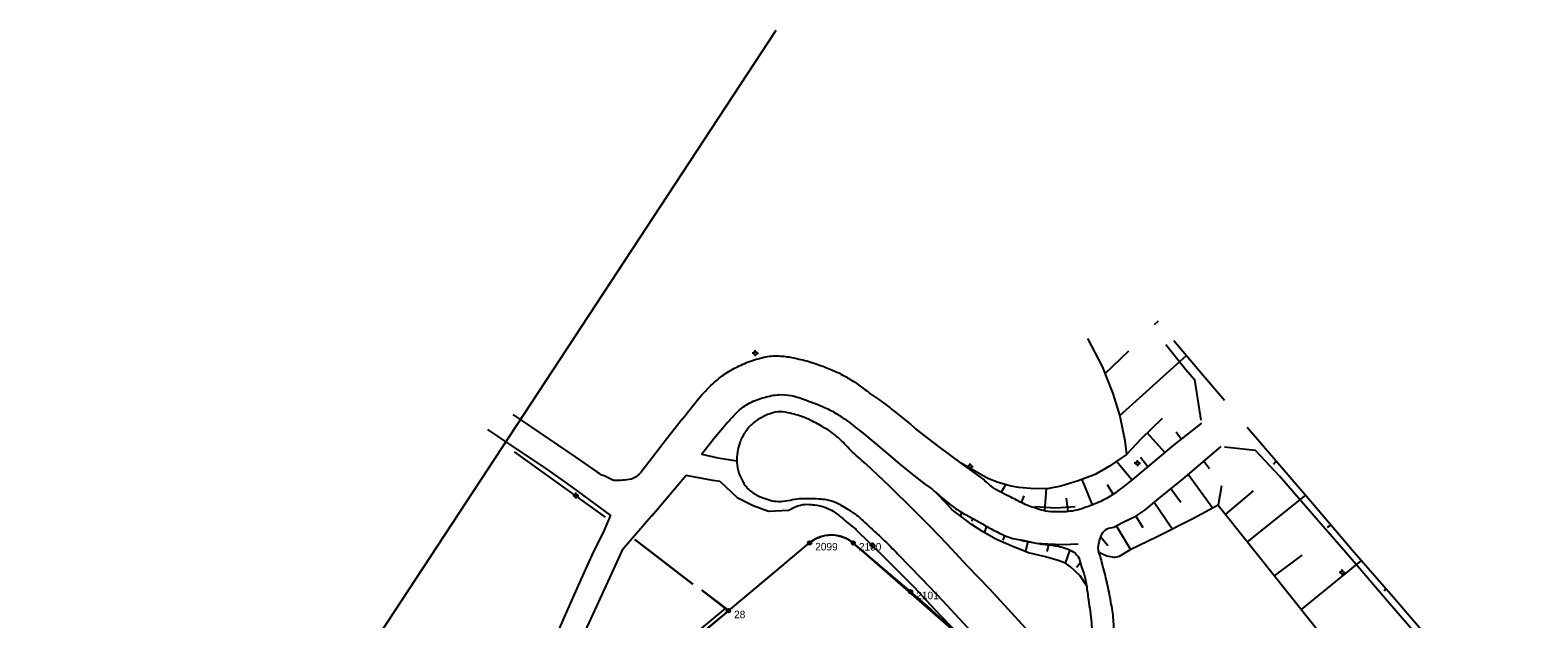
# Model space of a CAD drawing. Extents: x 1517478 to 1518189, y 6494860 to 6495389.
# Drawn here: x 1517883.6 to 1518083.7, y 6495240.6 to 6495318.7 of the extents above; entities that cross this region are included whole.
import ezdxf

# ---------------------------------------------------------------- set-up
doc = ezdxf.new("R2010")
doc.units = 0
for name, color, linetype in [('gc_vag', 7, 'Continuous'), ('grans', 7, 'Continuous'), ('granspunkt', 7, 'Continuous'), ('granspunkt_text', 7, 'Continuous'), ('hack', 7, 'Continuous'), ('kvartersgrans', 7, 'Continuous'), ('kvartersytor', 7, 'Continuous'), ('ledningar', 7, 'Continuous'), ('slant_skraffering', 7, 'Continuous'), ('slantfot', 7, 'Continuous'), ('slantkron', 7, 'Continuous'), ('staket', 7, 'Continuous'), ('stolpe_belysning', 7, 'Continuous'), ('vagkant', 7, 'Continuous')]:
    doc.layers.add(name, color=color, linetype=linetype)

msp = doc.modelspace()

# ---------------------------------------------------------------- linework, layer by layer
at = {"layer": 'gc_vag'}
for p, q in [((1517965.26, 6495260.82), (1517964.65, 6495260.03)), ((1517970.67, 6495259.61), (1517966.11, 6495254.21))]:
    msp.add_line(p, q, dxfattribs=at)
for points in [[(1517958.87, 6495260.1), (1517955.99, 6495262.08), (1517950.2, 6495266.03), (1517947.68, 6495267.69)], [(1517998.25, 6495268.16), (1518000.45, 6495266.43), (1518001.2, 6495265.76)], [(1517947.49, 6495263.61), (1517944.35, 6495265.74)], [(1517970.19, 6495267.12), (1517968.06, 6495264.42), (1517965.26, 6495260.82)], [(1517976.19, 6495266.7), (1517974.34, 6495264.49), (1517972.76, 6495262.43), (1517974.85, 6495261.97), (1517977.4, 6495261.55)], [(1517993.91, 6495265.4), (1517997.19, 6495262.67), (1517999.04, 6495261.12), (1518000.89, 6495259.61), (1518002.28, 6495258.52), (1518002.99, 6495258.03)], [(1518010.15, 6495259.08), (1518007.15, 6495261.25), (1518004.22, 6495263.42), (1518001.2, 6495265.76)], [(1518039.04, 6495266.56), (1518035.33, 6495263.64), (1518031.54, 6495260.45), (1518029.88, 6495259.08)], [(1517960.6, 6495254.37), (1517955.6, 6495258.02), (1517952.07, 6495260.53), (1517947.49, 6495263.61)], [(1518041.63, 6495263.45), (1518036.56, 6495259.17), (1518033.37, 6495256.57), (1518031.5, 6495255), (1518030.05, 6495254.06), (1518028.48, 6495253.3), (1518027.42, 6495252.7)], [(1517975.17, 6495258.82), (1517974.19, 6495258.97), (1517970.67, 6495259.61)], [(1517975.17, 6495258.82), (1517977.41, 6495256.72), (1517979.57, 6495255.64), (1517981.57, 6495254.87), (1517984.25, 6495255)], [(1517960.6, 6495254.37), (1517959.63, 6495252.05), (1517958.37, 6495249.52), (1517956.69, 6495245.83), (1517954.9, 6495241.83), (1517953.53, 6495238.72), (1517952.69, 6495236.93), (1517951.8, 6495234.88)], [(1517966.27, 6495254.47), (1517962.16, 6495249.73), (1517959.53, 6495243.94), (1517957.48, 6495239.51), (1517955.85, 6495235.83), (1517954.98, 6495233.83)], [(1517993.02, 6495252.63), (1517997.24, 6495248.49), (1518000.94, 6495244.79), (1518003.63, 6495241.91)], [(1518003.63, 6495241.88), (1518003.63, 6495241.91), (1518007.63, 6495237.7), (1518010.48, 6495234.7), (1518013.14, 6495232.03), (1518016.08, 6495228.73), (1518017.93, 6495226.61)]]:
    msp.add_lwpolyline(points, dxfattribs=at)
for points in [[(1517970.19, 6495267.12), (1517972.31, 6495269.79), (1517974.19, 6495271.79), (1517975.88, 6495273.13), (1517977.7, 6495274.16), (1517979.7, 6495274.95), (1517981.76, 6495275.43), (1517983.64, 6495275.43), (1517985.34, 6495275.13), (1517987.46, 6495274.58), (1517988.79, 6495274.1), (1517990.49, 6495273.43), (1517991.89, 6495272.7), (1517993.34, 6495271.79), (1517994.8, 6495270.7), (1517996.86, 6495269.25), (1517998.25, 6495268.16)], [(1517976.19, 6495266.7), (1517977.52, 6495268.1), (1517979.1, 6495269.25), (1517981.04, 6495269.98), (1517982.98, 6495270.34), (1517984.61, 6495270.22), (1517986.61, 6495269.61), (1517989.04, 6495268.64), (1517990.67, 6495267.79), (1517992.01, 6495266.88), (1517994.1, 6495265.25)], [(1517964.65, 6495260.03), (1517963.69, 6495259.26), (1517962.48, 6495259), (1517961.53, 6495258.95), (1517960.91, 6495259), (1517960.22, 6495259.37), (1517959.48, 6495259.68), (1517958.48, 6495260.37)], [(1518002.9, 6495258.1), (1518003.79, 6495257.38), (1518005.71, 6495255.76), (1518007.62, 6495254.49), (1518009.19, 6495253.64), (1518010.77, 6495252.74), (1518012.34, 6495251.93), (1518013.53, 6495251.42), (1518014.51, 6495251.17), (1518018.34, 6495250.45), (1518020.08, 6495250.23), (1518021.1, 6495249.94), (1518022.12, 6495249.43), (1518022.76, 6495248.7), (1518023.02, 6495247.85), (1518023.36, 6495246.87), (1518023.78, 6495245.04), (1518024.04, 6495243.13)], [(1518029.88, 6495259.08), (1518028.1, 6495257.68), (1518026.44, 6495256.57), (1518024.36, 6495255.64), (1518021.93, 6495254.91), (1518019.81, 6495254.79), (1518018.36, 6495254.91), (1518017.25, 6495255.21), (1518015.42, 6495255.89), (1518013.77, 6495256.74), (1518011.51, 6495257.93), (1518010.15, 6495259.08)], [(1517984.25, 6495255), (1517985.06, 6495255.42), (1517985.85, 6495255.7), (1517986.97, 6495255.79), (1517988, 6495255.67), (1517988.82, 6495255.49), (1517989.55, 6495255.21), (1517990.34, 6495254.76), (1517991, 6495254.27), (1517992.15, 6495253.3), (1517993.24, 6495252.46)], [(1518027.42, 6495252.7), (1518026.48, 6495252.49), (1518025.8, 6495251.81), (1518025.46, 6495250.91), (1518025.33, 6495249.72), (1518025.59, 6495248.87), (1518025.84, 6495247.94)], [(1518025.84, 6495247.94), (1518026.48, 6495245.38), (1518026.99, 6495242.87), (1518027.33, 6495240.49), (1518027.42, 6495238.32), (1518027.42, 6495236.58), (1518027.29, 6495234.53), (1518027.12, 6495232.83), (1518026.74, 6495230.96), (1518026.48, 6495229.68), (1518025.93, 6495228.11)], [(1518024.04, 6495243.13), (1518024.44, 6495240.07), (1518024.53, 6495237.26), (1518024.44, 6495235.17), (1518024.19, 6495233.39), (1518024.02, 6495231.81), (1518023.76, 6495230.62)]]:
    msp.add_spline(points, degree=3, dxfattribs=at)
at = {"layer": 'grans'}
for p, q in [((1517976.27, 6495241.68), (1517987.04, 6495250.68)), ((1518000.45, 6495244.2), (1517992.84, 6495250.66)), ((1517976.27, 6495241.68), (1517962.44, 6495230.13))]:
    msp.add_line(p, q, dxfattribs=at)
for centre, radius, start, end in [((1517989.93, 6495247.23), 4.5, 49.6994, 129.8503), ((1517907.57, 6495134.85), 143.47, 42.3829, 49.656)]:
    msp.add_arc(centre, radius, start, end, dxfattribs=at)
at = {"layer": 'granspunkt'}
for centre in [(1517987.04, 6495250.68), (1517992.84, 6495250.66), (1518000.45, 6495244.2), (1517976.27, 6495241.68)]:
    msp.add_circle(centre, 0.237, dxfattribs=at)
at = {"layer": 'hack'}
for p, q in [((1517959.97, 6495254.09), (1517947.86, 6495262.75)), ((1517971.53, 6495245.2), (1517963.85, 6495251.15)), ((1517972.74, 6495244.41), (1517976.21, 6495241.78))]:
    msp.add_line(p, q, dxfattribs=at)
at = {"layer": 'kvartersgrans'}
msp.add_line((1517992.84, 6495250.66), (1518000.45, 6495244.2), dxfattribs=at)
msp.add_lwpolyline([(1517962.44, 6495230.13), (1517976.27, 6495241.68), (1517987.04, 6495250.68)], dxfattribs=at)
for centre, radius, start, end in [((1517989.93, 6495247.23), 4.5, 49.6994, 129.8503), ((1517907.58, 6495134.86), 143.46, 42.3826, 49.6563)]:
    msp.add_arc(centre, radius, start, end, dxfattribs=at)
at = {"layer": 'kvartersytor'}
msp.add_lwpolyline([(1518074.11, 6495027.69), (1517921.04, 6495195.52), (1517981.66, 6495246.18), (1517987.04, 6495250.68), (1517987.4, 6495250.96), (1517987.81, 6495251.2), (1517988.26, 6495251.41), (1517988.58, 6495251.53), (1517989.03, 6495251.64), (1517989.55, 6495251.72), (1517989.95, 6495251.73), (1517990.42, 6495251.71), (1517990.85, 6495251.63), (1517991.35, 6495251.5), (1517991.85, 6495251.31), (1517992.28, 6495251.07), (1517992.57, 6495250.87), (1517992.84, 6495250.66), (1518007.2, 6495238.09), (1518015.81, 6495229.08), (1518018.08, 6495226.6), (1518024.14, 6495219.95), (1518073.64, 6495165.68), (1518099.97, 6495136.82)], dxfattribs=at)
at = {"layer": 'ledningar'}
msp.add_lwpolyline([(1517680.89, 6495088.62), (1517783.53, 6495114.28), (1517923.32, 6495228.43), (1517982.59, 6495318.69)], dxfattribs=at)
at = {"layer": 'slant_skraffering'}
for p, q in [((1518033.3, 6495280.11), (1518032.79, 6495279.6)), ((1518026.23, 6495273.12), (1518029.43, 6495276.17)), ((1518028.19, 6495267.54), (1518037.05, 6495275.53)), ((1518036.35, 6495264.44), (1518035.7, 6495265.38)), ((1518034.17, 6495262.66), (1518031.86, 6495265.28)), ((1518029.83, 6495259.04), (1518027.77, 6495261.49)), ((1518031.95, 6495260.79), (1518030.96, 6495262.02)), ((1518039.35, 6495261.53), (1518040.11, 6495260.53)), ((1518048.97, 6495261.51), (1518048.61, 6495261.08)), ((1518037.29, 6495259.79), (1518040.57, 6495255.3)), ((1518012.46, 6495257.35), (1518013.07, 6495258.41)), ((1518018.27, 6495254.93), (1518018.5, 6495257.89)), ((1518024.57, 6495255.72), (1518023.21, 6495259.11)), ((1518027.35, 6495257.14), (1518026.59, 6495258.38)), ((1518034.99, 6495257.89), (1518036.32, 6495256.08)), ((1518042.26, 6495254.44), (1518045.94, 6495257.6)), ((1518015.15, 6495256.03), (1518015.52, 6495256.92)), ((1518021.35, 6495254.83), (1518021.13, 6495256.63)), ((1518032.79, 6495256.08), (1518035.22, 6495252.52)), ((1518045.17, 6495250.8), (1518052.87, 6495256.95)), ((1518007.2, 6495254.73), (1518007.03, 6495254.18)), ((1518008.66, 6495253.93), (1518008.56, 6495253.53)), ((1518030.33, 6495254.24), (1518031.29, 6495252.73)), ((1518010.26, 6495252.04), (1518010.57, 6495252.86)), ((1518012.93, 6495251.66), (1518012.71, 6495251.05)), ((1518025.66, 6495251.54), (1518026.63, 6495250.32)), ((1518027.78, 6495252.9), (1518029.63, 6495249.79)), ((1518056.22, 6495253.01), (1518055.75, 6495252.7)), ((1518018.76, 6495250.39), (1518018.54, 6495249.52)), ((1518021.57, 6495249.74), (1518020.96, 6495248)), ((1518022.97, 6495248), (1518022.48, 6495247.4)), ((1518048.75, 6495246.29), (1518052.4, 6495249.06)), ((1518052.31, 6495241.83), (1518060.26, 6495248.29)), ((1518063.49, 6495244.61), (1518063.3, 6495244.27))]:
    msp.add_line(p, q, dxfattribs=at)
msp.add_lwpolyline([(1518016.02, 6495250.89), (1518015.7, 6495249.52), (1518015.7, 6495249.52)], dxfattribs=at)
at = {"layer": 'slantfot'}
msp.add_line((1518042.1, 6495263.42), (1518046.2, 6495262.98), dxfattribs=at)
for points in [[(1518034.33, 6495277), (1518036.96, 6495273.68), (1518038.11, 6495272.36), (1518038.98, 6495266.98)], [(1518033.82, 6495267.18), (1518031.03, 6495264.49), (1518029.1, 6495262.4), (1518026.86, 6495260.87), (1518024.95, 6495259.76), (1518022.7, 6495258.91), (1518020.4, 6495258.19), (1518018.78, 6495257.89), (1518016.87, 6495257.85), (1518014.79, 6495258.02), (1518013.81, 6495258.19), (1518012.07, 6495258.7), (1518010.7, 6495259.21), (1518007.15, 6495261.25)], [(1518058.2, 6495249.4), (1518054, 6495254.22), (1518049.39, 6495259.54), (1518046.23, 6495262.95)], [(1518023.78, 6495245.04), (1518022.97, 6495246.32), (1518022.25, 6495246.96), (1518021.66, 6495247.51), (1518021.02, 6495247.98), (1518020.04, 6495248.36), (1518018.34, 6495248.83), (1518016.08, 6495249.38), (1518013.79, 6495250.28), (1518011.75, 6495251.17), (1518010, 6495252.19), (1518008.47, 6495253.17), (1518007.32, 6495254.06), (1518005.96, 6495255.08), (1518005.32, 6495255.81), (1518003.79, 6495257.38)], [(1518041.71, 6495258.26), (1518041.28, 6495255.68), (1518037.92, 6495253.89), (1518033.16, 6495251.47), (1518029.59, 6495249.77), (1518028.14, 6495248.87), (1518027.5, 6495248.75), (1518026.48, 6495248.92), (1518025.76, 6495249.26), (1518025.41, 6495249.47)], [(1518074.04, 6495230.84), (1518068.84, 6495237.08), (1518064.02, 6495242.66), (1518058.2, 6495249.4)]]:
    msp.add_lwpolyline(points, dxfattribs=at)
at = {"layer": 'slantkron'}
msp.add_lwpolyline([(1518023.91, 6495277.8), (1518025.86, 6495274.06), (1518027.27, 6495270.49), (1518028.2, 6495267.51), (1518028.88, 6495264.27), (1518029.1, 6495262.4)], dxfattribs=at)
at = {"layer": 'staket'}
msp.add_line((1517963.85, 6495251.15), (1517971.53, 6495245.2), dxfattribs=at)
for points in [[(1518022.29, 6495255.47), (1518019.74, 6495255.3), (1518016.93, 6495255.47)], [(1518041.26, 6495255.67), (1518042.34, 6495254.35), (1518055.52, 6495237.8)], [(1518015.11, 6495251.08), (1518017.1, 6495250.66), (1518018.64, 6495250.57), (1518020.63, 6495250.45), (1518021.66, 6495250.53), (1518022.68, 6495250.57)], [(1517956.11, 6495225.56), (1517975.9, 6495241.99), (1517972.74, 6495244.41)]]:
    msp.add_lwpolyline(points, dxfattribs=at)
at = {"layer": 'stolpe_belysning'}
for p, q in [((1517979.64, 6495275.85), (1517979.44, 6495275.85)), ((1517979.84, 6495276.05), (1517979.84, 6495276.25)), ((1517979.84, 6495275.65), (1517979.84, 6495275.45)), ((1517980.04, 6495275.85), (1517980.24, 6495275.85)), ((1518030.54, 6495261.45), (1518030.54, 6495261.65)), ((1518008.14, 6495260.83), (1518007.94, 6495260.83)), ((1518008.34, 6495261.03), (1518008.34, 6495261.23)), ((1518008.34, 6495260.63), (1518008.34, 6495260.43)), ((1518008.54, 6495260.83), (1518008.74, 6495260.83)), ((1518030.34, 6495261.25), (1518030.14, 6495261.25)), ((1518030.54, 6495261.05), (1518030.54, 6495260.85)), ((1518030.74, 6495261.25), (1518030.94, 6495261.25)), ((1517956, 6495257.15), (1517956, 6495257.35)), ((1517955.8, 6495256.95), (1517955.6, 6495256.95)), ((1517956, 6495256.75), (1517956, 6495256.55)), ((1517956.2, 6495256.95), (1517956.4, 6495256.95)), ((1517995.19, 6495250.34), (1517994.99, 6495250.34)), ((1517995.39, 6495250.54), (1517995.39, 6495250.74)), ((1517995.39, 6495250.14), (1517995.39, 6495249.94)), ((1517995.59, 6495250.34), (1517995.79, 6495250.34)), ((1518057.52, 6495246.77), (1518057.32, 6495246.77)), ((1518057.72, 6495246.97), (1518057.72, 6495247.17)), ((1518057.72, 6495246.57), (1518057.72, 6495246.37)), ((1518057.92, 6495246.77), (1518058.12, 6495246.77))]:
    msp.add_line(p, q, dxfattribs=at)
for centre in [(1517979.84, 6495275.85), (1518030.54, 6495261.25), (1518008.34, 6495260.83), (1517956, 6495256.95), (1517995.39, 6495250.34), (1518057.72, 6495246.77)]:
    msp.add_circle(centre, 0.2, dxfattribs=at)
at = {"layer": 'vagkant'}
for points in [[(1518035.39, 6495277.51), (1518039.22, 6495272.95), (1518042.09, 6495269.61)], [(1518059.3, 6495249.4), (1518053.5, 6495256.21), (1518045.13, 6495266)], [(1517994.44, 6495261.23), (1517997.61, 6495258.27), (1518000.8, 6495255.09), (1518003.01, 6495252.88), (1518005.25, 6495250.57), (1518008.01, 6495247.6), (1518010.86, 6495244.63)], [(1518075.88, 6495230.24), (1518071.22, 6495235.67), (1518064.8, 6495243.12), (1518059.3, 6495249.4)], [(1517998.77, 6495249.18), (1518001.95, 6495245.9), (1518004.68, 6495243.05)], [(1518010.86, 6495244.63), (1518013.86, 6495241.39), (1518017.01, 6495237.93), (1518020.13, 6495234.6), (1518022.62, 6495232.02), (1518023.76, 6495230.64)], [(1518004.68, 6495243.05), (1518007.95, 6495239.48), (1518013.83, 6495233.35), (1518019.86, 6495226.68)]]:
    msp.add_lwpolyline(points, dxfattribs=at)
for points in [[(1517994.49, 6495261.18), (1517992.52, 6495262.94), (1517990.83, 6495264.64), (1517988.7, 6495266.13), (1517987.01, 6495267.03), (1517985.49, 6495267.61), (1517984.46, 6495267.88), (1517983.16, 6495268.07), (1517981.82, 6495267.82), (1517980.43, 6495267.19), (1517979.37, 6495266.4), (1517978.46, 6495265.31), (1517977.79, 6495264), (1517977.46, 6495262.73), (1517977.4, 6495261.37), (1517977.67, 6495259.91), (1517978.19, 6495258.82), (1517978.49, 6495258.3), (1517979.64, 6495257.24), (1517981.01, 6495256.6), (1517982.07, 6495256.27), (1517983.16, 6495256.18), (1517984.49, 6495256.36), (1517985.67, 6495256.57), (1517986.92, 6495256.57), (1517988.28, 6495256.54), (1517989.25, 6495256.42), (1517989.95, 6495256.27), (1517991.37, 6495255.6), (1517992.25, 6495255.06), (1517993.43, 6495254.27)], [(1517993.43, 6495254.27), (1517995.34, 6495252.48), (1517996.74, 6495251.21), (1517998.77, 6495249.18)]]:
    msp.add_spline(points, degree=3, dxfattribs=at)

# ---------------------------------------------------------------- texts
at = {"layer": 'granspunkt_text'}
for s, p in [('2099', (1517987.79, 6495249.68)), ('2100', (1517993.59, 6495249.66)), ('2101', (1518001.2, 6495243.2)), ('28', (1517977.02, 6495240.68))]:
    msp.add_text(s, height=1, dxfattribs=at).set_placement(p)

doc.saveas('drawing.dxf')
